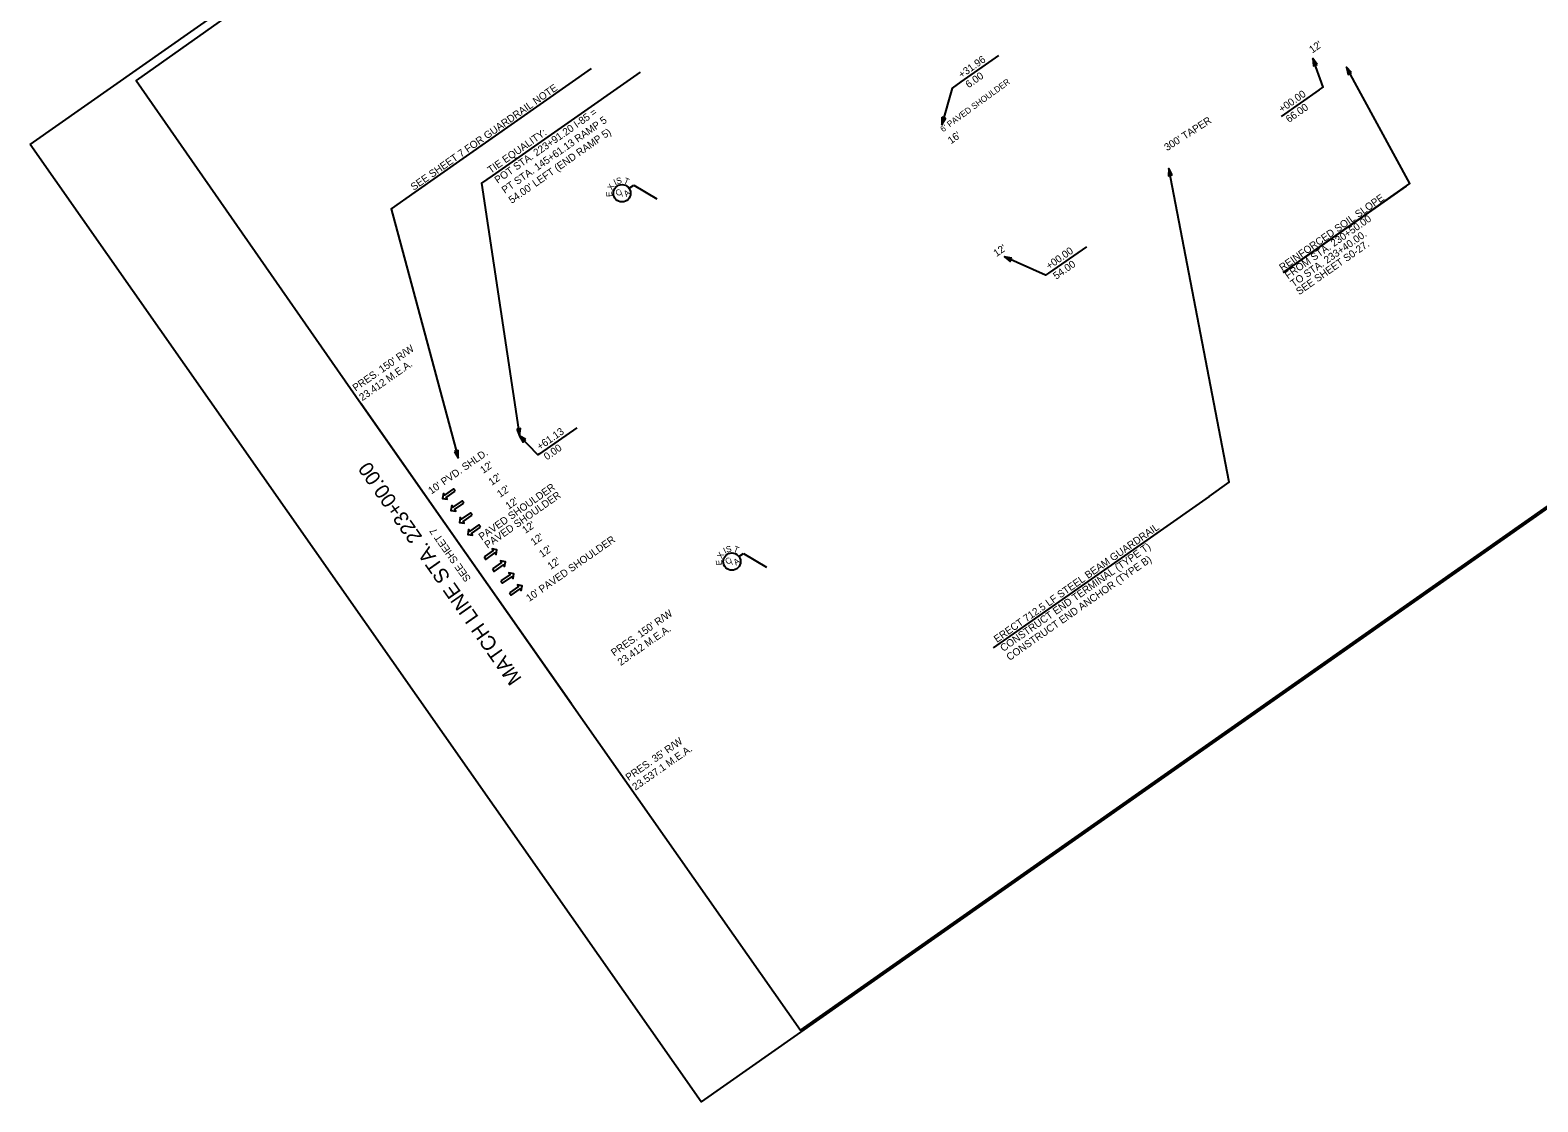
# Model space of a CAD drawing. Extents: x 1604963 to 1606883, y 1089540 to 1091304.
# Drawn here: x 1604963 to 1606197, y 1089540 to 1090417 of the extents above; entities that cross this region are included whole.
import ezdxf

# ---------------------------------------------------------------- set-up
doc = ezdxf.new("R2010")
doc.units = 0
for name, color, linetype in [('RD_DTM_Obscure', 7, 'Continuous'), ('RD_EX_Bldg', 7, 'Continuous'), ('RD_EX_BldgApp', 7, 'Continuous'), ('RD_EX_Fence_Other', 7, 'Continuous'), ('RD_EX_H2O_WetLd', 7, 'Continuous'), ('RD_EX_Misc', 7, 'Continuous'), ('RD_EX_Misc_Golf_Teebox', 7, 'Continuous'), ('RD_EX_UT', 7, 'Continuous'), ('RD_EX_VEG', 7, 'Continuous')]:
    doc.layers.add(name, color=color, linetype=linetype)

msp = doc.modelspace()

# ---------------------------------------------------------------- linework, layer by layer
at = {"layer": 'RD_DTM_Obscure'}
for p, q in [((1605452.9, 1090287.3), (1605456.7, 1090289.9)), ((1605456.7, 1090289.9), (1605475.5, 1090278.7)), ((1605542.8, 1089986), (1605546.5, 1089988.6)), ((1605546.5, 1089988.6), (1605565.3, 1089977.4))]:
    msp.add_line(p, q, dxfattribs=at)
for centre in [(1605447.1, 1090283.2), (1605537, 1089981.9)]:
    msp.add_circle(centre, 7.08, dxfattribs=at)
at = {"layer": 'RD_EX_Bldg'}
msp.add_lwpolyline([(1604962.8, 1090323), (1606334.1, 1091284.8), (1606883.3, 1090501.8), (1605512, 1089539.9)], close=True, dxfattribs=at)
at = {"layer": 'RD_EX_Fence_Other'}
msp.add_lwpolyline([(1604962.8, 1090323), (1606334.1, 1091284.8), (1606883.3, 1090501.8), (1605512, 1089539.9)], close=True, dxfattribs=at)
at = {"layer": 'RD_EX_H2O_WetLd'}
for p, q in [((1605422, 1090385.3), (1605277.6, 1090284)), ((1605927.5, 1090035.2), (1605750.8, 1089911.2))]:
    msp.add_line(p, q, dxfattribs=at)
for points in [[(1605897.4, 1090298.2), (1605894.7, 1090303.6), (1605894.3, 1090297.6)], [(1605310.1, 1090071.9), (1605313.1, 1090066.7), (1605313.1, 1090072.7)]]:
    msp.add_lwpolyline(points, close=True, dxfattribs=at)
for points in [[(1605927.5, 1090035.2), (1605944, 1090046.8), (1605894.7, 1090303.6)], [(1605277.6, 1090284), (1605258.3, 1090270.5), (1605313.1, 1090066.7)]]:
    msp.add_lwpolyline(points, dxfattribs=at)
at = {"layer": 'RD_EX_Misc'}
for points in [[(1605310.7, 1090039.5), (1605309.3, 1090041.5), (1605301.8, 1090036.2), (1605300.9, 1090037.5), (1605300.2, 1090033.6), (1605304.1, 1090032.9), (1605303.2, 1090034.2)], [(1605317.6, 1090029.7), (1605316.2, 1090031.6), (1605308.7, 1090026.4), (1605307.8, 1090027.7), (1605307.1, 1090023.8), (1605311, 1090023.1), (1605310.1, 1090024.4)], [(1605324.5, 1090019.9), (1605323.1, 1090021.8), (1605315.6, 1090016.6), (1605314.7, 1090017.9), (1605314, 1090014), (1605317.9, 1090013.3), (1605317, 1090014.6)], [(1605331.4, 1090010), (1605330, 1090012), (1605322.5, 1090006.7), (1605321.5, 1090008.1), (1605320.8, 1090004.1), (1605324.8, 1090003.4), (1605323.9, 1090004.8)], [(1605334.2, 1089985.7), (1605335.6, 1089983.7), (1605343.1, 1089989), (1605344.1, 1089987.7), (1605344.8, 1089991.6), (1605340.8, 1089992.3), (1605341.8, 1089991)], [(1605341.1, 1089975.9), (1605342.5, 1089973.9), (1605350, 1089979.2), (1605351, 1089977.8), (1605351.7, 1089981.8), (1605347.7, 1089982.5), (1605348.6, 1089981.1)], [(1605348, 1089966.1), (1605349.4, 1089964.1), (1605356.9, 1089969.4), (1605357.9, 1089968), (1605358.5, 1089972), (1605354.6, 1089972.7), (1605355.5, 1089971.3)], [(1605354.9, 1089956.2), (1605356.3, 1089954.3), (1605363.8, 1089959.5), (1605364.7, 1089958.2), (1605365.4, 1089962.1), (1605361.5, 1089962.8), (1605362.4, 1089961.5)]]:
    msp.add_lwpolyline(points, close=True, dxfattribs=at)
at = {"layer": 'RD_EX_Misc_Golf_Teebox'}
for p, q in [((1605755.3, 1090395.9), (1605724.5, 1090374.4)), ((1605461.9, 1090382.4), (1605340.8, 1090297.5)), ((1606017.5, 1090367.8), (1605986.6, 1090346.1)), ((1606088.7, 1090289), (1605988.1, 1090218.5)), ((1605827.1, 1090239.4), (1605796.2, 1090217.8)), ((1605410, 1090091.4), (1605379.5, 1090070)), ((1605357.1, 1090014.9), (1605357.1, 1090014.9))]:
    msp.add_line(p, q, dxfattribs=at)
for points in [[(1606017.5, 1090367.8), (1606020.8, 1090370.1), (1606012.5, 1090393.6)], [(1605988.1, 1090218.5), (1606091.7, 1090291.1), (1606040, 1090386.3)], [(1605724.5, 1090374.4), (1605717.3, 1090369.3), (1605708.8, 1090339.4)], [(1605340.8, 1090297.5), (1605332.1, 1090291.4), (1605363.3, 1090084.8)], [(1605796.2, 1090217.8), (1605793.8, 1090216.1), (1605760, 1090231.2)], [(1605379.5, 1090070), (1605378.2, 1090069.1), (1605363.3, 1090084.8)]]:
    msp.add_lwpolyline(points, dxfattribs=at)
for points in [[(1606015.9, 1090388.7), (1606012.5, 1090393.6), (1606013, 1090387.6)], [(1606044.2, 1090381.9), (1606040, 1090386.3), (1606041.4, 1090380.5)], [(1605708.9, 1090345.4), (1605708.8, 1090339.4), (1605711.9, 1090344.5)], [(1605766, 1090230.2), (1605760, 1090231.2), (1605764.7, 1090227.4)], [(1605360.9, 1090090.3), (1605363.3, 1090084.8), (1605364, 1090090.8)], [(1605368.5, 1090081.7), (1605363.3, 1090084.8), (1605366.2, 1090079.5)]]:
    msp.add_lwpolyline(points, close=True, dxfattribs=at)
at = {"layer": 'RD_EX_UT'}
msp.add_lwpolyline([(1605233.6, 1090111), (1605405.8, 1089865.4), (1605593.1, 1089598.4), (1606815.9, 1090456.1), (1606682.3, 1090657.8), (1606533, 1090870.5), (1606535.9, 1090871.8), (1606406.7, 1091049.1), (1606294.2, 1091212.3), (1606168.2, 1091123.2), (1606148, 1091151.8), (1605049.4, 1090375.5)], close=True, dxfattribs=at)
msp.add_lwpolyline([(1605233.6, 1090111), (1605405.8, 1089865.4), (1605593.1, 1089598.4), (1606815.9, 1090456.1), (1606682.3, 1090657.8), (1606533, 1090870.5), (1606535.9, 1090871.8), (1606406.7, 1091049.1), (1606294.2, 1091212.3), (1606168.2, 1091123.2), (1606148, 1091151.8), (1605049.4, 1090375.5)], close=True, dxfattribs=at)
at = {"layer": 'RD_EX_VEG'}
msp.add_lwpolyline([(1605405.8, 1089865.4), (1605319.7, 1089988.2), (1605233.6, 1090111)], dxfattribs=at)

# ---------------------------------------------------------------- texts
at = {"layer": 'RD_DTM_Obscure'}
for s, rotation, p in [('X', 60.1403, (1605439, 1090285.2)), ('I', 24.9789, (1605441.6, 1090289.6)), ('S', 13.2584, (1605443, 1090290.6)), ('T', 338.0969, (1605448, 1090291.6)), ('E', 93.6275, (1605439.2, 1090280.4)), ('C', 35.0436, (1605443.8, 1090280.4)), ('/', 35.0436, (1605447.4, 1090280.4)), ('A', 35.0436, (1605450.6, 1090280)), ('S', 13.2584, (1605532.8, 1089989.2)), ('T', 338.0969, (1605537.8, 1089990.3)), ('E', 93.6275, (1605529.1, 1089979)), ('X', 60.1403, (1605528.8, 1089983.9)), ('I', 24.9789, (1605531.4, 1089988.2)), ('C', 35.0436, (1605533.6, 1089979.1)), ('/', 35.0436, (1605537.3, 1089979.1)), ('A', 35.0436, (1605540.4, 1089978.6))]:
    msp.add_text(s, height=5, rotation=rotation, dxfattribs=at).set_placement(p)
at = {"layer": 'RD_EX_BldgApp'}
for s, p in [("PRES. 150' R/W", (1605229.2, 1090120.9)), ('23.412 M.E.A.', (1605234.6, 1090113.1)), ("PRES. 150' R/W", (1605440.7, 1089904.2)), ('23.412 M.E.A.', (1605446.1, 1089896.4)), ("PRES. 35' R/W", (1605452.6, 1089802.2)), ('23.537.1 M.E.A.', (1605458.1, 1089794.4))]:
    msp.add_text(s, height=6, rotation=35.0468, dxfattribs=at).set_placement(p)
at = {"layer": 'RD_EX_H2O_WetLd'}
for s, rotation, p in [('SEE SHEET 7 FOR GUARDRAIL NOTE', 35.0468, (1605276.7, 1090285.2)), ('ERECT 712.5 LF STEEL BEAM GUARDRAIL', 35.0485, (1605754, 1089915.3)), ('CONSTRUCT END TERMINAL (TYPE T)', 35.0485, (1605759.2, 1089907.9)), ('CONSTRUCT END ANCHOR (TYPE B)', 35.0485, (1605764.3, 1089900.5))]:
    msp.add_text(s, height=6, rotation=rotation, dxfattribs=at).set_placement(p)
at = {"layer": 'RD_EX_Misc_Golf_Teebox'}
for s, height, rotation, p in [("12'", 6, 35.0436, (1606012, 1090397.5)), ('+31.96', 6, 35.0468, (1605725, 1090377.1)), ('6.00', 6, 35.0468, (1605730.8, 1090369)), ("6' PAVED SHOULDER", 5, 36.0871, (1605709.8, 1090333)), ('+00.00', 6, 35.0468, (1605987.1, 1090348.9)), ('66.00', 6, 35.0468, (1605992.9, 1090340.7)), ('POT STA. 223+91.20 I-85 =', 6, 35.0452, (1605345.4, 1090290.9)), ('PT STA. 145+61.13 RAMP 5', 6, 35.0452, (1605351.2, 1090282.7)), ("300' TAPER", 6, 32.7562, (1605893.2, 1090317.6)), ('TIE EQUALITY:', 6, 35.0452, (1605339.7, 1090299.1)), ("54.00' LEFT (END RAMP 5)", 6, 35.0452, (1605356.9, 1090274.5)), ("16'", 6, 36.0638, (1605716.4, 1090323.2)), ('REINFORCED SOIL SLOPE', 6, 35.0485, (1605987.5, 1090219.3)), ('FROM STA. 230+50.00', 6, 35.0485, (1605992.1, 1090212.8)), ("12'", 6, 35.0436, (1605753.6, 1090231)), ('TO STA. 233+40.00.', 6, 35.0485, (1605996.7, 1090206.2)), ('SEE SHEET S0-27.', 6, 35.0485, (1606001.3, 1090199.7)), ('+00.00', 6, 35.0468, (1605796.7, 1090220.6)), ('54.00', 6, 35.0468, (1605802.5, 1090212.4)), ('+61.13', 6, 35.0468, (1605380, 1090072.8)), ("10' PVD. SHLD.", 6, 35.0452, (1605291.1, 1090036.7)), ('0.00', 6, 35.0468, (1605385.7, 1090064.6)), ("12'", 6, 35.0436, (1605333.6, 1090053.6)), ('PAVED SHOULDER', 6, 35.0452, (1605332.4, 1089999)), ("12'", 6, 35.0436, (1605340.5, 1090043.8)), ("12'", 6, 35.0436, (1605347.4, 1090034)), ('PAVED SHOULDER', 6, 35.0452, (1605337.1, 1089992.4)), ("12'", 6, 35.0436, (1605354.3, 1090024.2)), ("12'", 6, 35.0436, (1605368, 1090004.5)), ("10' PAVED SHOULDER", 6, 35.0452, (1605371.2, 1089948.8)), ("12'", 6, 35.0436, (1605374.9, 1089994.7)), ("12'", 6, 35.0436, (1605381.8, 1089984.9)), ("12'", 6, 35.0436, (1605388.7, 1089975))]:
    msp.add_text(s, height=height, rotation=rotation, dxfattribs=at).set_placement(p)
at = {"layer": 'RD_EX_VEG'}
for s, height, rotation, p in [('MATCH LINE STA. 223+00.00', 12, 125.0468, (1605365.5, 1089886.1)), ('SEE SHEET 7', 6, 125.0981, (1605323.8, 1089967.9))]:
    msp.add_text(s, height=height, rotation=rotation, dxfattribs=at).set_placement(p)

doc.saveas('drawing.dxf')
